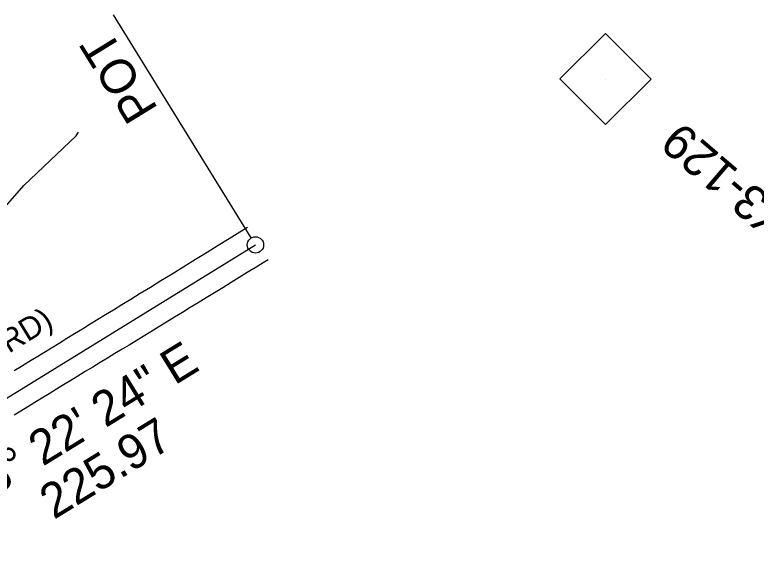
# Model space of a CAD drawing. Extents: x 478596 to 483012, y 490885 to 495165.
# Drawn here: x 481192.2 to 481532.8, y 493242.3 to 493492.2 of the extents above; entities that cross this region are included whole.
import ezdxf

# ---------------------------------------------------------------- set-up
doc = ezdxf.new("R2010")
doc.units = 0
for name, color, linetype in [('CTL Secondary Horizontal and Vertical CELL', 7, 'Continuous'), ('CTL Secondary Horizontal and Vertical Text', 7, 'Continuous'), ('Exist Horizontal Alignment', 7, 'Continuous'), ('Exist Horizontal Alignment Direction Label', 7, 'Continuous'), ('Exist Roads EOP', 7, 'Continuous'), ('Exist Roads EOP Text', 7, 'Continuous'), ('Exist Vegetation Hedge Row', 7, 'Continuous')]:
    doc.layers.add(name, color=color, linetype=linetype)

msp = doc.modelspace()

# ---------------------------------------------------------------- linework, layer by layer
at = {"layer": 'CTL Secondary Horizontal and Vertical CELL'}
msp.add_line((481463.49, 493462.63), (481463.49, 493462.63), dxfattribs=at)
msp.add_lwpolyline([(481442.63, 493462.7), (481463.59, 493483.67), (481484.59, 493462.67), (481463.63, 493441.7)], close=True, dxfattribs=at)
at = {"layer": 'Exist Horizontal Alignment'}
for p, q in [((481300.79, 493389.59), (481237.58, 493492.23)), ((481110.35, 493267.91), (481302.76, 493386.4))]:
    msp.add_line(p, q, dxfattribs=at)
msp.add_circle((481302.76, 493386.4), 3.75, dxfattribs=at)
at = {"layer": 'Exist Roads EOP'}
for points in [[(481191.95, 493328.62), (481195.23, 493330.65), (481198.58, 493332.72), (481201.99, 493334.82), (481205.47, 493336.94), (481208.99, 493339.1), (481212.53, 493341.26), (481216.1, 493343.44), (481219.68, 493345.64), (481223.26, 493347.83), (481226.82, 493350.01), (481230.35, 493352.18), (481233.86, 493354.33), (481237.48, 493356.55), (481241.36, 493358.92), (481245.48, 493361.44), (481249.84, 493364.12), (481254.46, 493366.96), (481259.33, 493369.96), (481264.45, 493373.13), (481269.82, 493376.47), (481275.24, 493379.83), (481280.52, 493383.1), (481285.66, 493386.28), (481290.66, 493389.35), (481295.53, 493392.35), (481299.15, 493394.57)], [(481308.61, 493379.48), (481306.36, 493378.1), (481302.68, 493375.86), (481299.01, 493373.63), (481295.29, 493371.36), (481291.53, 493369.05), (481287.71, 493366.71), (481283.9, 493364.36), (481280.15, 493362.05), (481276.46, 493359.77), (481272.82, 493357.54), (481269.2, 493355.32), (481265.58, 493353.09), (481261.94, 493350.87), (481258.29, 493348.64), (481254.69, 493346.44), (481251.22, 493344.32), (481247.88, 493342.28), (481244.66, 493340.31), (481241.46, 493338.36), (481238.19, 493336.37), (481234.84, 493334.33), (481231.42, 493332.26), (481227.98, 493330.17), (481224.58, 493328.1), (481221.21, 493326.05), (481217.89, 493324.02), (481214.58, 493322), (481211.27, 493319.97), (481207.96, 493317.94), (481204.65, 493315.91), (481201.37, 493313.89), (481198.15, 493311.9), (481195, 493309.94), (481191.91, 493308.01)]]:
    msp.add_lwpolyline(points, dxfattribs=at)
at = {"layer": 'Exist Vegetation Hedge Row'}
msp.add_lwpolyline([(481132.08, 493341.18), (481145.94, 493360.08), (481174.9, 493389.4), (481196.39, 493413.68), (481220.33, 493436.62), (481221.43, 493438.24)], dxfattribs=at)

# ---------------------------------------------------------------- texts
at = {"layer": 'CTL Secondary Horizontal and Vertical Text'}
msp.add_text('BY3-129', height=16, rotation=139.3796, dxfattribs=at).set_placement((481561.51, 493389.41))
at = {"layer": 'Exist Horizontal Alignment'}
msp.add_text('POT', height=16, rotation=121.6268, dxfattribs=at).set_placement((481258.28, 493448.94))
at = {"layer": 'Exist Horizontal Alignment Direction Label'}
for s, p in [('N 58%%d 22\' 24" E', (481154.21, 493253.04)), ('225.97', (481210.15, 493259.84))]:
    msp.add_text(s, height=16, rotation=31.6268, dxfattribs=at).set_placement(p)
at = {"layer": 'Exist Roads EOP Text'}
msp.add_text('SR 1556 (MARTINS CREEK RD)', height=10.4, rotation=31.5156, dxfattribs=at).set_placement((481035.31, 493241.79))

doc.saveas('drawing.dxf')
